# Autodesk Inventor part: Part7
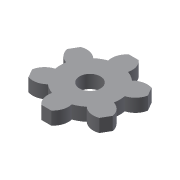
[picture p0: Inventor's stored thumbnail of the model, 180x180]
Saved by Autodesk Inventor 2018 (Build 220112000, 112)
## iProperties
Shininess: 77.0
Angle Display Precision: 2
Document Length Units: 11269
Document Angle Units: 11279
Document Time Units: 11290
Document Mass Units: 11283
Document Length Units Precision: 3
Document Angle Units Precision: 2
Created: 2002-01
Part Number: Part7
Document SubType Name: Modeling
Designer: ***
Density: 1 g/cm^3
Material: Generic
Appearance: Default
Density: 0.0
Volumn: 0.0
Area: 0.0
PropertySet Name: Model Information
Control State: 0
Master: False
Checked Out: False
Author: ***
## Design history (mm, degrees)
sketch "Sketch1"
  geometry: L1 (-3.771, 33.333)-(3.771, 33.333); L2 (-30.753, 13.401)-(-26.982, 19.933); L3 (-30.753, -13.401)-(-26.982, -19.933); L4 (-3.771, -33.333)-(3.771, -33.333); L5 (30.753, 13.401)-(26.982, 19.933); L6 (30.753, -13.401)-(26.982, -19.933); C1 r 8 at (0, 0); A1 r 11.863 centre (3.952, 24.328) between (-3.771, 33.333) and (-7.559, 21.457); A2 r 11.863 centre (-3.952, 24.328) between (7.559, 21.457) and (3.771, 33.333); A3 r 11.863 centre (-19.093, 15.587) between (-30.753, 13.401) and (-22.362, 4.182); A4 r 11.863 centre (-23.045, 8.742) between (-14.803, 17.275) and (-26.982, 19.933); A5 r 22.749 centre (0, 0) between (-7.559, 21.457) and (-14.803, 17.275); A6 r 11.863 centre (-23.045, -8.742) between (-26.982, -19.933) and (-14.803, -17.275); A7 r 11.863 centre (-19.093, -15.587) between (-22.362, -4.182) and (-30.753, -13.401); A8 r 11.863 centre (3.952, -24.328) between (-7.559, -21.457) and (-3.771, -33.333); A9 r 11.863 centre (-3.952, -24.328) between (3.771, -33.333) and (7.559, -21.457); A10 r 11.863 centre (23.045, 8.742) between (26.982, 19.933) and (14.803, 17.275); A11 r 11.863 centre (19.093, 15.587) between (22.362, 4.182) and (30.753, 13.401); A12 r 11.863 centre (19.093, -15.587) between (30.753, -13.401) and (22.362, -4.182); A13 r 11.863 centre (23.045, -8.742) between (14.803, -17.275) and (26.982, -19.933); A14 r 22.749 centre (0, 0) between (-22.362, 4.182) and (-22.362, -4.182); A15 r 22.749 centre (0, 0) between (-14.803, -17.275) and (-7.559, -21.457); A16 r 22.749 centre (0, 0) between (7.559, -21.457) and (14.803, -17.275); A17 r 22.749 centre (0, 0) between (22.362, -4.182) and (22.362, 4.182); A18 r 22.749 centre (0, 0) between (14.803, 17.275) and (7.559, 21.457)
  constraints: 36 point on circle, 19 centre point, 12 end point, 1 coincident
  dimensions: "d2" = 16 diameter of C1
extrude "Extrusion1" new body sketch "Sketch1" distance "d0" = 10; taper "d1" = 0 deg
body "Solid1"
